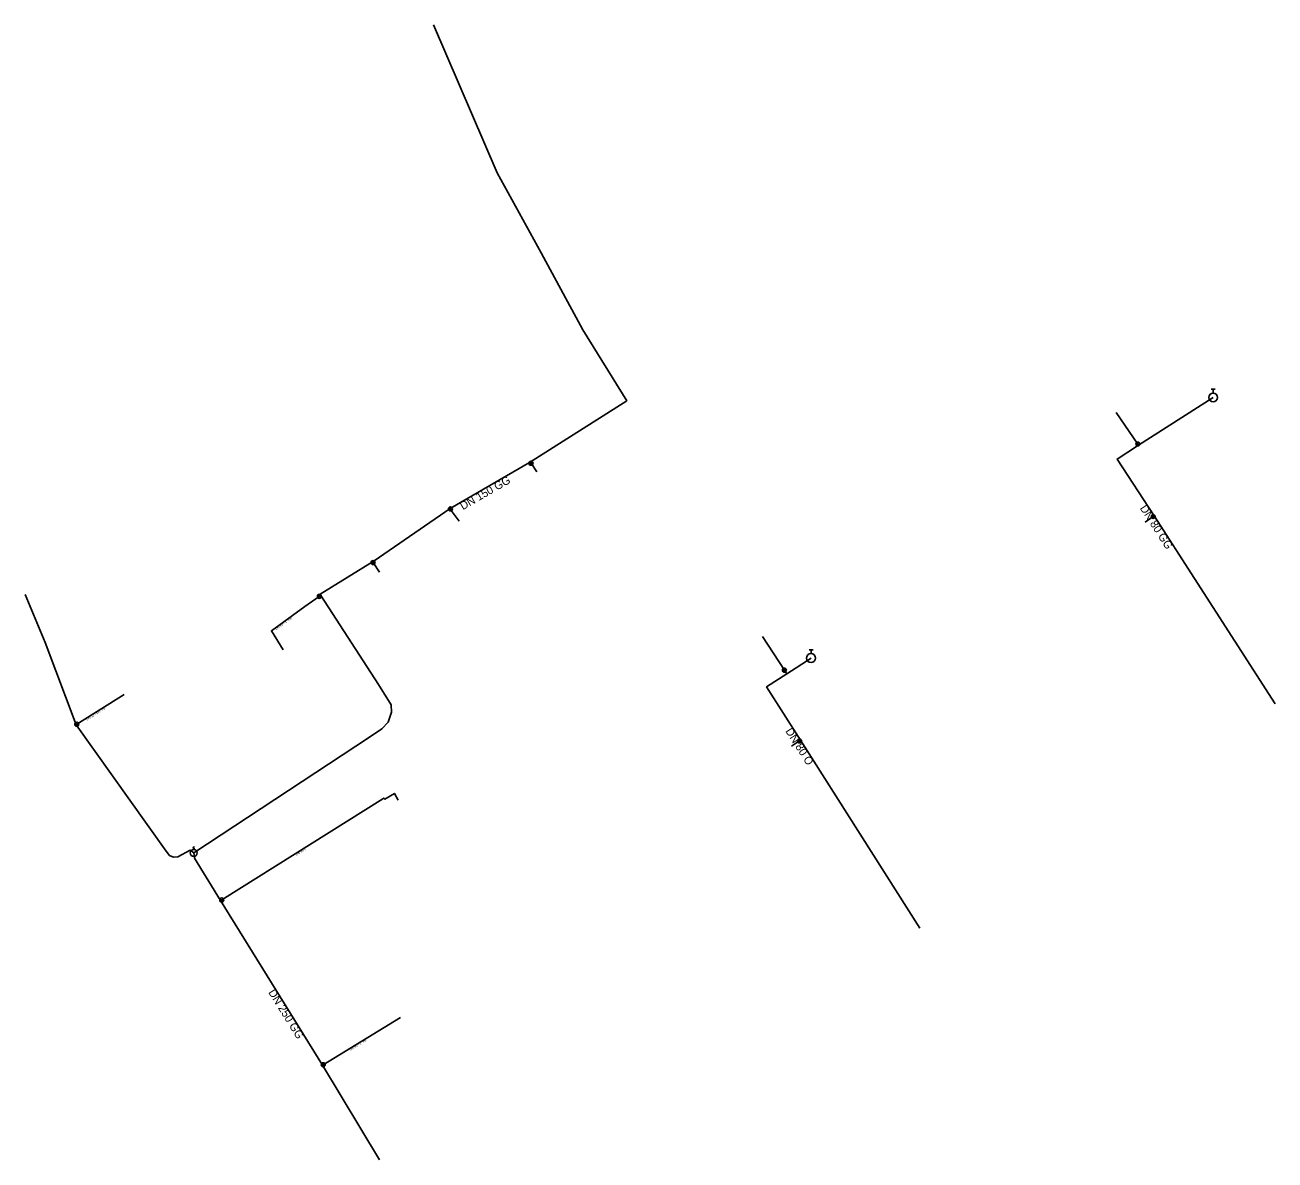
# Model space of a CAD drawing. Extents: x -451199 to -450721, y -1101768 to -1101453.
# Drawn here: x -451199.3 to -450948.8, y -1101768.3 to -1101540.7 of the extents above; entities that cross this region are included whole.
import ezdxf

# ---------------------------------------------------------------- set-up
doc = ezdxf.new("R2010")
doc.units = 0
for name, color, linetype in [('_pripojka_prevzato_z_dokumentace_', 7, 'Continuous'), ('_pripojka_priblizne_', 7, 'Continuous'), ('_voda_smvak_prevzato_z_dokumentace_', 7, 'Continuous'), ('Default', 7, 'Continuous'), ('MoLevel 28', 7, 'Continuous'), ('MoLevel 30', 7, 'Continuous'), ('MoLevel 46', 7, 'Continuous'), ('MoLevel 53', 7, 'Continuous'), ('MoLevel 55', 7, 'Continuous')]:
    doc.layers.add(name, color=color, linetype=linetype)

# ---------------------------------------------------------------- blocks, each defined once
blk = doc.blocks.new('_uzaver_pripojka_')
at = {"layer": 'Default'}
for p, q in [((-0.000035, -0.000035), (0.000035, 0.000035)), ((0.000035, -0.000035), (-0.000035, 0.000035))]:
    blk.add_line(p, q, dxfattribs=at)
for radius in [0.00005, 0.0000025]:
    blk.add_circle((0, 0), radius, dxfattribs=at)
blk = doc.blocks.new('_hydrant_voda_')
at = {"layer": 'Default'}
for p, q in [((-0.000023, 0.000095), (0.000023, 0.000095)), ((0, 0.000095), (0, 0.00005))]:
    blk.add_line(p, q, dxfattribs=at)
blk.add_circle((0, 0), 0.00005, dxfattribs=at)
blk = doc.blocks.new('_sachta_voda_')
at = {"layer": 'Default'}
blk.add_lwpolyline([(0.000007, 0.00006), (-0.000006, 0.000057), (-0.000003, 0.000051), (0.000003, 0.000048), (0.000006, 0.000043), (-0.000007, 0.000038), (-0.000008, 0.00004)], dxfattribs=at)
blk.add_circle((0, 0), 0.000035, dxfattribs=at)

msp = doc.modelspace()

# ---------------------------------------------------------------- linework, layer by layer
at = {"layer": '_pripojka_prevzato_z_dokumentace_'}
for points in [[(-450976.11, -1101624.98), (-450976.23, -1101624.74), (-450980.61, -1101618.43)], [(-451098.18, -1101628.47), (-451097.89, -1101628.61), (-451096.72, -1101630.29)], [(-451114.12, -1101637.65), (-451113.87, -1101638.07), (-451112.29, -1101640.22)], [(-450972.98, -1101639.17), (-450973.17, -1101639.27), (-450974.78, -1101640.42)], [(-451129.36, -1101648.16), (-451129.56, -1101648.51), (-451128.28, -1101650.45)], [(-451140.05, -1101655.1), (-451140.33, -1101655.29), (-451143.22, -1101657.33), (-451149.95, -1101662.19), (-451147.56, -1101666.03)], [(-451046.59, -1101670.83), (-451047.1, -1101670.09), (-451051.49, -1101663.33)], [(-451189.05, -1101681.03), (-451188.95, -1101680.95), (-451179.47, -1101674.99)], [(-451043.9, -1101684.14), (-451044.07, -1101684.29), (-451045.69, -1101685.31)], [(-451160.14, -1101716.29), (-451159.9, -1101716.17), (-451127.58, -1101695.86)], [(-451139.69, -1101749.28), (-451139.55, -1101749.2), (-451124.05, -1101739.75)]]:
    msp.add_lwpolyline(points, dxfattribs=at)
at = {"layer": '_pripojka_priblizne_'}
msp.add_lwpolyline([(-451127.58, -1101695.86), (-451127.39, -1101695.74), (-451127.22, -1101695.96), (-451125.29, -1101694.81), (-451124.5, -1101696.15)], dxfattribs=at)
at = {"layer": '_voda_smvak_prevzato_z_dokumentace_'}
for points in [[(-451117.44, -1101540.72), (-451104.69, -1101570.35), (-451095.87, -1101586.4), (-451095.39, -1101587.26), (-451087.5, -1101601.84), (-451078.69, -1101616.06), (-451098.18, -1101628.47), (-451114.12, -1101637.65), (-451129.36, -1101648.16), (-451140.18, -1101654.85), (-451140.05, -1101655.1), (-451128.48, -1101672.98), (-451125.92, -1101677.04), (-451125.87, -1101678.53), (-451126.51, -1101680.52), (-451127.77, -1101681.88), (-451130.24, -1101683.54), (-451165.51, -1101706.74)], [(-450961.14, -1101615.4), (-450976.11, -1101624.98), (-450980.41, -1101627.75), (-450972.98, -1101639.17), (-450948.75, -1101676.86)], [(-451199.33, -1101654.94), (-451195.28, -1101664.57), (-451189.05, -1101681.03), (-451171.04, -1101706.41), (-451170.34, -1101707.27), (-451169.57, -1101707.57), (-451168.7, -1101707.55), (-451166.23, -1101706.2), (-451165.51, -1101706.74)], [(-451041.76, -1101667.66), (-451046.59, -1101670.83), (-451050.66, -1101673.46), (-451043.9, -1101684.14), (-451019.95, -1101721.83)], [(-451165.51, -1101706.74), (-451165.34, -1101707.76), (-451160.14, -1101716.29), (-451139.69, -1101749.28), (-451128.25, -1101768.31)]]:
    msp.add_lwpolyline(points, dxfattribs=at)

# ---------------------------------------------------------------- block references
at = {"layer": 'MoLevel 28', "xscale": 17636.68430335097, "yscale": 17636.68430335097}
for p in [(-450961.14, -1101615.4), (-451041.76, -1101667.66)]:
    msp.add_blockref('_hydrant_voda_', p, dxfattribs=at)
at = {"layer": 'MoLevel 30', "xscale": 20000, "yscale": 20000}
msp.add_blockref('_sachta_voda_', (-451165.51, -1101706.74), dxfattribs=at)
at = {"layer": 'MoLevel 53', "xscale": 7999.999999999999, "yscale": 7999.999999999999}
for p in [(-450976.23, -1101624.74), (-451097.89, -1101628.61), (-451114.05, -1101637.77), (-450973.17, -1101639.27), (-451129.56, -1101648.51), (-451140.33, -1101655.29), (-451047.1, -1101670.09), (-451188.95, -1101680.95), (-451044.07, -1101684.29), (-451159.9, -1101716.17), (-451139.55, -1101749.2)]:
    msp.add_blockref('_uzaver_pripojka_', p, dxfattribs=at)

# ---------------------------------------------------------------- texts
at = {"layer": 'MoLevel 46'}
for s, rotation, p in [('DN 150 GG', 29.9381, (-451111.56, -1101638.03)), ('DN 80 GG', 302.736, (-450975.9, -1101637.6)), ('DN 80 O', 302.4338, (-451046.97, -1101682.3)), ('DN 250 GG', 301.7942, (-451150.62, -1101734.69))]:
    msp.add_text(s, height=1.605, rotation=rotation, dxfattribs=at).set_placement(p)
at = {"layer": 'MoLevel 55'}
for s, rotation, p in [("DN 25 - 1'' PE", 35.8345, (-451148.96, -1101662.04)), ("DN 32 - 5/4'' PE", 32.1572, (-451186.89, -1101680.19)), ('DN 80 L', 32.1465, (-451144.91, -1101707.28)), ("DN 50 - 2'' PE", 31.3697, (-451134.14, -1101746.43))]:
    msp.add_text(s, height=0.455, rotation=rotation, dxfattribs=at).set_placement(p)

doc.saveas('drawing.dxf')
